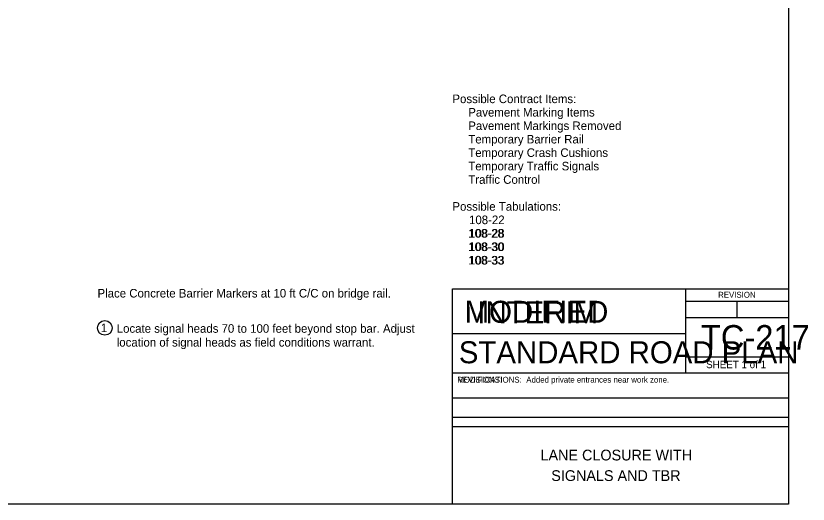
# Model space of a CAD drawing. Extents: x -2134934 to -2127057, y -2139046 to -2137036.
# Drawn here: x -2128679 to -2127057, y -2139046 to -2138047 of the extents above; entities that cross this region are included whole.
import ezdxf

# ---------------------------------------------------------------- set-up
doc = ezdxf.new("R2010")
doc.units = 0
for name, color, linetype in [('BridgeSuperStructureExisting', 7, 'Continuous'), ('Default', 7, 'Continuous'), ('Dimension', 7, 'Continuous'), ('dsnAlignmentCurveData', 7, 'Continuous'), ('dsnAlignmentTic', 7, 'Continuous'), ('dsnCellElements', 7, 'Continuous'), ('hwyPlanSheetShape', 7, 'Continuous')]:
    doc.layers.add(name, color=color, linetype=linetype)

msp = doc.modelspace()

# ---------------------------------------------------------------- linework, layer by layer
at = {"layer": 'BridgeSuperStructureExisting'}
msp.add_circle((-2128496.7, -2138685.5), 15, dxfattribs=at)
at = {"layer": 'Default'}
msp.add_lwpolyline([(-2130232, -2137035.9), (-2127097, -2137035.9), (-2127097, -2139045.9), (-2130232, -2139045.9)], close=True, dxfattribs=at)
at = {"layer": 'Dimension'}
for p, q in [((-2127307.9, -2138605.9), (-2127307.9, -2138697.3)), ((-2127307.9, -2138630.9), (-2127097, -2138630.9)), ((-2127202.4, -2138630.9), (-2127202.4, -2138664.1)), ((-2127307.9, -2138664.1), (-2127097, -2138664.1)), ((-2127785, -2138697.3), (-2127307.9, -2138697.3)), ((-2127307.9, -2138697.3), (-2127307.9, -2138777.3)), ((-2127097, -2138745.1), (-2127307.9, -2138745.1)), ((-2127785, -2138777.3), (-2127097, -2138777.3)), ((-2127785, -2138828.3), (-2127097, -2138828.3)), ((-2127785, -2138868.3), (-2127097, -2138868.3)), ((-2127785, -2138887.3), (-2127097, -2138887.3))]:
    msp.add_line(p, q, dxfattribs=at)
msp.add_lwpolyline([(-2127785, -2138605.9), (-2127097, -2138605.9), (-2127097, -2139045.9), (-2127785, -2139045.9)], close=True, dxfattribs=at)

# ---------------------------------------------------------------- texts
at = {"layer": 'BridgeSuperStructureExisting'}
for s, p in [('1', (-2128504.8, -2138694.2)), ('Locate signal heads 70 to 100 feet beyond stop bar. Adjust ', (-2128472.3, -2138695.5)), ('location of signal heads as field conditions warrant.', (-2128472.3, -2138723.8))]:
    msp.add_text(s, height=17.5, dxfattribs=at).set_placement(p)
at = {"layer": 'Dimension'}
for s, height, p in [('REVISION', 12, (-2127240.9, -2138623.8)), ('TC-217', 50, (-2127276.2, -2138729.8)), ('STANDARD ROAD PLAN', 45.001, (-2127771.9, -2138757.9)), ('SHEET 1 of 1', 15, (-2127265.5, -2138767.9)), ('Added private entrances near work zone.', 12, (-2127633.7, -2138797.5)), ('LANE CLOSURE WITH', 22, (-2127604.6, -2138956.6)), ('SIGNALS AND TBR', 22, (-2127582.6, -2138998.6))]:
    msp.add_text(s, height=height, dxfattribs=at).set_placement(p)
at = {"layer": 'dsnAlignmentCurveData'}
msp.add_text('REVISIONS:', height=12, dxfattribs=at).set_placement((-2127775, -2138797.6))
at = {"layer": 'dsnAlignmentTic'}
for s, height, p in [('MODIFIED', 45, (-2127759.9, -2138675.1)), ('MODIFICATIONS:', 12, (-2127775, -2138797.6))]:
    msp.add_text(s, height=height, dxfattribs=at).set_placement(p)
at = {"layer": 'dsnCellElements'}
for s, p in [('Possible Contract Items:', (-2127785, -2138225.9)), ('     Pavement Marking Items', (-2127785, -2138253.4)), ('     Pavement Markings Removed', (-2127785, -2138280.9)), ('     Temporary Barrier Rail', (-2127785, -2138308.4)), ('     Temporary Crash Cushions', (-2127785, -2138335.9)), ('     Temporary Traffic Signals', (-2127785, -2138363.4)), ('     Traffic Control', (-2127785, -2138390.9)), ('Possible Tabulations:', (-2127785, -2138445.9)), ('108-22', (-2127751, -2138473.3)), ('108-22', (-2127751, -2138473.4)), ('     108-28', (-2127785, -2138500.9)), ('108-28', (-2127751, -2138500.9)), ('     108-30', (-2127785, -2138528.4)), ('108-30', (-2127751, -2138528.4)), ('     108-33', (-2127785, -2138555.9)), ('108-33', (-2127751.1, -2138555.9)), ('Place Concrete Barrier Markers at 10 ft C/C on bridge rail.', (-2128511.7, -2138623.4))]:
    msp.add_text(s, height=17.5, dxfattribs=at).set_placement(p)
at = {"layer": 'hwyPlanSheetShape'}
msp.add_text('INTERIM', height=45, dxfattribs=at).set_placement((-2127734, -2138676.3))

doc.saveas('drawing.dxf')
